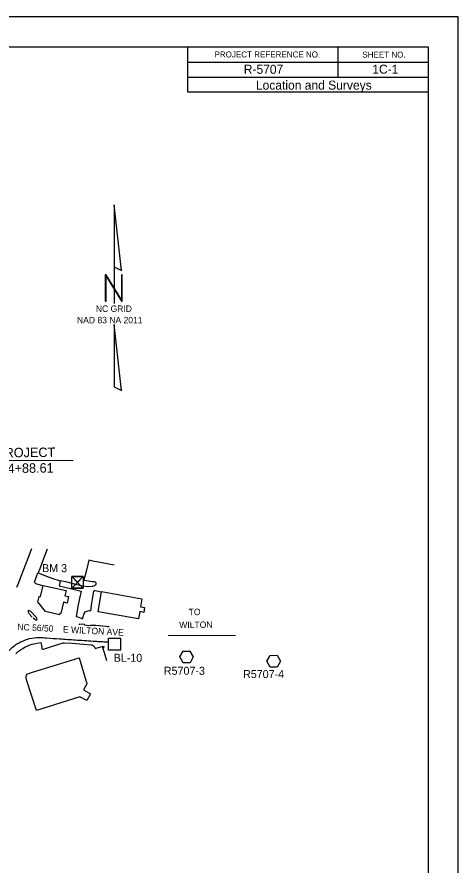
# Model space of a CAD drawing. Extents: x 2088830 to 2093930, y 861854 to 865154.
# Drawn here: x 2092828 to 2093930, y 863035 to 865154 of the extents above; entities that cross this region are included whole.
import ezdxf

# ---------------------------------------------------------------- set-up
doc = ezdxf.new("R2010")
doc.units = 0
for name, color, linetype in [('CTL North Arrow NAD 83 NA 2011 CELL', 7, 'Continuous'), ('CTL Primary Horizontal and Vertical CELL', 7, 'Continuous'), ('Default', 7, 'Continuous'), ('Exist Building', 7, 'Continuous'), ('Exist Roads Change in Surface', 7, 'Continuous'), ('Exist Roads Curbs', 7, 'Continuous'), ('Exist Roads EOP', 7, 'Continuous'), ('Exist Roads EOP Leader', 7, 'Continuous'), ('Exist Roads EOP Other', 7, 'Continuous'), ('Exist Roads EOP Text', 7, 'Continuous'), ('Exist Roads Soil', 7, 'Continuous'), ('Sheet Data Field CELL', 7, 'Continuous'), ('Sheet Plan CELL', 7, 'Continuous'), ('Sheet Plot Border Inside CELL', 7, 'Continuous')]:
    doc.layers.add(name, color=color, linetype=linetype)

msp = doc.modelspace()

# ---------------------------------------------------------------- linework, layer by layer
at = {"layer": 'CTL North Arrow NAD 83 NA 2011 CELL'}
msp.add_line((2093071.2, 864452.7), (2093071.2, 864452.7), dxfattribs=at)
for points in [[(2093070.8, 864685.1), (2093070.8, 864529.8), (2093089.1, 864520.7)], [(2093048.9, 864444.1), (2093050.7, 864444.1), (2093050.7, 864506.1), (2093089.1, 864444.1), (2093090.9, 864444.1), (2093090.9, 864509.8), (2093089.1, 864509.8), (2093089.1, 864447.7), (2093050.7, 864509.8), (2093048.9, 864509.8)], [(2093070.8, 864230.3), (2093089.1, 864221.2), (2093070.8, 864385.6)]]:
    msp.add_lwpolyline(points, close=True, dxfattribs=at)
msp.add_lwpolyline([(2093070.8, 864529.8), (2093070.8, 864438.5)], dxfattribs=at)
at = {"layer": 'CTL Primary Horizontal and Vertical CELL'}
for p, q in [((2093251.9, 863555), (2093251.9, 863555)), ((2093469.4, 863544.2), (2093469.4, 863544.2))]:
    msp.add_line(p, q, dxfattribs=at)
for points in [[(2093260.4, 863569.9), (2093268.8, 863555), (2093260.7, 863540.1), (2093243.6, 863540.2), (2093234.8, 863555.1), (2093243.1, 863569.8)], [(2093478, 863559.1), (2093486.4, 863544.2), (2093478.2, 863529.2), (2093461.1, 863529.3), (2093452.4, 863544.2), (2093460.6, 863559)]]:
    msp.add_lwpolyline(points, close=True, dxfattribs=at)
at = {"layer": 'Default'}
for p, q in [((2092968.7, 864045.5), (2092633.9, 864045.4)), ((2092979.4, 863741.4), (2092979.4, 863741.4)), ((2093071.8, 863586.9), (2093071.8, 863586.9))]:
    msp.add_line(p, q, dxfattribs=at)
for points in [[(2092965, 863755.7), (2092993.7, 863755.7), (2092993.7, 863727), (2092965, 863727)], [(2093057.1, 863601.7), (2093086.7, 863601.8), (2093086.8, 863572.1), (2093057.2, 863572)]]:
    msp.add_lwpolyline(points, close=True, dxfattribs=at)
for points in [[(2092993.7, 863755.7), (2092965, 863727), (2092979.3, 863741.3), (2092993.7, 863727), (2092965, 863755.7)], [(2092979.3, 863741.3), (2092993.7, 863755.7), (2092965, 863755.7), (2092979.3, 863741.3)], [(2092979.3, 863741.3), (2092965, 863727), (2092993.7, 863727), (2092979.3, 863741.3)]]:
    msp.add_lwpolyline(points, dxfattribs=at)
at = {"layer": 'Exist Building'}
for p, q in [((2092862.1, 863669.1), (2092858.6, 863670.5)), ((2092877, 863653.4), (2092862.1, 863669.1)), ((2092878.6, 863651), (2092877, 863653.4)), ((2092998.6, 863504.3), (2092998.1, 863504.3))]:
    msp.add_line(p, q, dxfattribs=at)
for points in [[(2092934.7, 863660.1), (2092899.1, 863668.7), (2092880.4, 863692.5), (2092883.5, 863706.3), (2092886.9, 863705.9), (2092893.5, 863733.9), (2092951, 863720.8), (2092948.1, 863708.1), (2092957.1, 863706.1), (2092953.3, 863689.7), (2092944.2, 863691.8), (2092938, 863663.6), (2092935.3, 863664.2)], [(2092876.6, 863421.4), (2092852.2, 863498.2), (2092850.8, 863503.4), (2092851, 863506.4), (2092852, 863509.2), (2092853.5, 863511.7), (2092856.6, 863514.1), (2092866.6, 863516.8), (2092929.7, 863535.8), (2092983.4, 863552.5), (2093001.4, 863493.7), (2093002.4, 863490.4), (2093003, 863488.1), (2092994.3, 863472.8), (2093011.7, 863463), (2093003, 863446.4), (2092985.2, 863455.8), (2092876.6, 863421.4)]]:
    msp.add_lwpolyline(points, close=True, dxfattribs=at)
msp.add_lwpolyline([(2093131.8, 863650.2), (2093031.1, 863668.1), (2093039.7, 863718.2), (2093140.4, 863700), (2093137.1, 863680.6), (2093147.1, 863678.6), (2093145, 863666.4), (2093135.4, 863668.3), (2093131.8, 863650.2)], dxfattribs=at)
at = {"layer": 'Exist Roads Change in Surface'}
msp.add_lwpolyline([(2092893.3, 863732.8), (2092877.4, 863736.9), (2092874.7, 863738.6), (2092872.4, 863741.8)], dxfattribs=at)
at = {"layer": 'Exist Roads Curbs'}
msp.add_line((2092997.2, 863635.5), (2092997, 863635.9), dxfattribs=at)
for points in [[(2092903.4, 863824), (2092895.4, 863802.6), (2092885.2, 863775.6), (2092881.2, 863764.9)], [(2092825.1, 863562.9), (2092832.3, 863569.1), (2092837.3, 863573.1), (2092842.4, 863576.4), (2092848.3, 863580), (2092853.3, 863582.4), (2092858.5, 863584.7), (2092866.2, 863587.3), (2092878.4, 863589.9), (2092888.2, 863591.4), (2092890, 863579.1), (2092890.3, 863576.8), (2092890.6, 863575.8), (2092891.3, 863575), (2092892.2, 863574.7), (2092894.7, 863574.9), (2092912.1, 863580.4), (2092930.6, 863586.2), (2092943.3, 863590.1), (2092945.8, 863590.5), (2092966, 863589.1), (2092994.4, 863587.2), (2093013.3, 863585.4), (2093015.6, 863585), (2093017.2, 863584.4), (2093019.1, 863582.9), (2093020.9, 863581.4), (2093022.3, 863579.5), (2093023.4, 863577.7), (2093023.9, 863576.9), (2093024.8, 863576.5), (2093026.1, 863576.8), (2093037.7, 863580.3), (2093041.5, 863581.3), (2093043.9, 863581.6), (2093046.3, 863580.9)], [(2093046.1, 863577.8), (2093043.8, 863578.2), (2093041.9, 863578.4), (2093045.8, 863566.1), (2093052, 863546.3)]]:
    msp.add_lwpolyline(points, dxfattribs=at)
msp.add_spline([(2093058.5, 863630.4), (2093050.6, 863631), (2093016.7, 863633.4), (2092998, 863634.5), (2092997.4, 863634.8), (2092997.2, 863635.5)], degree=3, dxfattribs=at)
at = {"layer": 'Exist Roads EOP'}
for p, q in [((2092856.8, 863671.6), (2092858.4, 863671.6)), ((2092871.7, 863649.5), (2092868.8, 863651.9)), ((2093045.5, 863593.1), (2093055.8, 863593.1))]:
    msp.add_line(p, q, dxfattribs=at)
for points in [[(2092828.2, 863729.3), (2092832.6, 863740.8), (2092838.9, 863757.2), (2092844.5, 863772), (2092850.1, 863786.9), (2092855.9, 863801.7), (2092861.9, 863817.4), (2092865.3, 863826)], [(2092872.2, 863741.8), (2092880.7, 863765)]]:
    msp.add_lwpolyline(points, dxfattribs=at)
for points in [[(2092866.3, 863654.5), (2092864.7, 863656.3), (2092863.1, 863658.1), (2092858.5, 863663.7), (2092856.7, 863669.6), (2092856.8, 863671.6)], [(2092878.4, 863649.8), (2092878.1, 863648.5), (2092877.6, 863647.5), (2092876.7, 863646.8), (2092875.1, 863647.3), (2092871.7, 863649.5)], [(2092783.6, 863530.8), (2092785.6, 863535.1), (2092792.7, 863549.7), (2092807.5, 863570), (2092820.6, 863582.3), (2092829.8, 863588.7), (2092831.8, 863589.7), (2092836.8, 863592.5), (2092839.1, 863593.5), (2092859.8, 863601.1), (2092883.2, 863603.7), (2092901.8, 863602.7), (2092935.1, 863600.4), (2092973.9, 863597.7), (2093018.3, 863594.8), (2093029.6, 863594), (2093045.5, 863593.1)]]:
    msp.add_spline(points, degree=3, dxfattribs=at)
at = {"layer": 'Exist Roads EOP Leader'}
msp.add_line((2093374.1, 863607.7), (2093206.4, 863608.5), dxfattribs=at)
at = {"layer": 'Exist Roads EOP Other'}
for points in [[(2092880.7, 863765), (2092883, 863764.2), (2092889.3, 863761.7), (2092899.4, 863757.7), (2092915.7, 863751.7), (2092936.2, 863745.4), (2092933.3, 863732.8), (2092965.6, 863725), (2092988.7, 863719.4), (2092984.7, 863701), (2092980.6, 863681.5), (2092977.6, 863665.6), (2092976.1, 863656.3), (2092982.7, 863654.1), (2092992.1, 863650), (2092994.4, 863658.2), (2092996.3, 863663.8), (2092998.9, 863668), (2093002.7, 863669.7), (2093008.3, 863671), (2093011.8, 863670.3)], [(2093039.5, 863717.3), (2093027.9, 863719.3), (2093022.6, 863720.3), (2093021.3, 863720), (2093019.7, 863718.7), (2093018.5, 863715.1), (2093017.1, 863704.3), (2093014.7, 863689.7), (2093011.8, 863670.3)], [(2092997.1, 863636), (2092983.8, 863636.8), (2092983.5, 863635.7)], [(2092983.2, 863552.5), (2092983.2, 863552.4)]]:
    msp.add_lwpolyline(points, dxfattribs=at)
at = {"layer": 'Exist Roads Soil'}
msp.add_lwpolyline([(2093070.8, 863784.1), (2093040.5, 863789.8), (2093017.4, 863794.2), (2093007.8, 863796.5), (2093003, 863774.8), (2092995.4, 863747), (2093012, 863744.6), (2093016.9, 863743.9), (2093021, 863743.4), (2093023.5, 863742.5), (2093024.8, 863741.7), (2093025.2, 863739.3), (2093024.9, 863736.7), (2093024, 863734.3), (2093022.1, 863732.6), (2093016.8, 863730.8), (2093005.3, 863730.2), (2092992.9, 863731.7), (2092977.6, 863735.5), (2092953.3, 863741.9), (2092936.2, 863745.4)], dxfattribs=at)
at = {"layer": 'Sheet Plan CELL'}
for p, q in [((2093630.4, 865003.9), (2093630.4, 865079.1)), ((2093255.2, 865041.4), (2093855.3, 865041.4)), ((2093255.2, 865003.8), (2093855.3, 865003.9))]:
    msp.add_line(p, q, dxfattribs=at)
for points in [[(2089355.3, 865079.1), (2093855.3, 865079.1), (2093855.3, 861929.1), (2089355.3, 861929.1)], [(2093255.2, 865079.1), (2093855.3, 865079.1), (2093855.3, 864966.4), (2093255.2, 864966.4)]]:
    msp.add_lwpolyline(points, close=True, dxfattribs=at)
at = {"layer": 'Sheet Plot Border Inside CELL'}
msp.add_lwpolyline([(2093930.3, 865154.1), (2088830.3, 865154.1), (2088830.3, 861854.1), (2093930.3, 861854.1)], close=True, dxfattribs=at)

# ---------------------------------------------------------------- texts
at = {"layer": 'CTL North Arrow NAD 83 NA 2011 CELL'}
for s, height, p in [('NC GRID', 15.97, (2093025.3, 864417.2)), ('NAD 83 NA 2011', 15.972, (2092978.2, 864388.8))]:
    msp.add_text(s, height=height, dxfattribs=at).set_placement(p)
at = {"layer": 'Default'}
for s, rotation, p in [('END TIP PROJECT ', 0.4878, (2092643, 864052.4)), ('-L-  STA. 34+88.61', 0.6038, (2092652, 864013))]:
    msp.add_text(s, height=23.633, rotation=rotation, dxfattribs=at).set_placement(p)
for s, p in [('BM 3', (2092890.9, 863766.9)), ('BL-10', (2093069.8, 863542.9)), ('R5707-3', (2093195.2, 863510.5)), ('R5707-4', (2093393.1, 863502.3))]:
    msp.add_text(s, height=20, dxfattribs=at).set_placement(p)
at = {"layer": 'Exist Roads EOP Text'}
for s, rotation, p in [('TO', 0.5773, (2093257.2, 863659.3)), ('NC 56/50    E WILTON AVE  ', 356.8603, (2092828.7, 863622.6)), ('WILTON', 0.5773, (2093233.7, 863627.1))]:
    msp.add_text(s, height=16, rotation=rotation, dxfattribs=at).set_placement(p)
at = {"layer": 'Sheet Data Field CELL'}
for s, p in [('R-5707', (2093394.9, 865012.1)), ('1C-1', (2093716, 865012.3))]:
    msp.add_text(s, height=22.5, rotation=0, dxfattribs=at).set_placement(p)
at = {"layer": 'Sheet Plan CELL'}
for s, height, p in [('PROJECT REFERENCE NO.', 15, (2093321.8, 865052.9)), ('SHEET NO.', 15, (2093691.3, 865052.6)), ('Location and Surveys', 22.5, (2093425.2, 864972.5))]:
    msp.add_text(s, height=height, rotation=0, dxfattribs=at).set_placement(p)

doc.saveas('drawing.dxf')
